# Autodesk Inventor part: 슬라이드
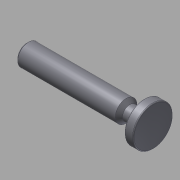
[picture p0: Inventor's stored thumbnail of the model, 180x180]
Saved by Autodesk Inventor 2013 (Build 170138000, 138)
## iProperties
Company: 한국ATC센터
Created: 2015-12
Part Number: 슬라이드
Document SubType Name: Modeling
Designer: mdu
Density: 7.86 g/cm^3
Mass: 68.0563 g
Surface Area: 34.7349 cm^2
Volume: 8.65856 cm^3
Material: 강철, 연강
Author: mdu
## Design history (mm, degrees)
sketch "스케치1"
  geometry: L1 (-35, 0)-(35, 0); L2 (35, 0)-(35, 11); L3 (35, 11)-(30, 11); L4 (30, 11)-(30, 4); L5 (30, 4)-(22, 4); L6 (22, 4)-(20, 6); L7 (20, 6)-(-35, 6); L8 (-35, 6)-(-35, 0); 1 further point
  constraints: 16 end point, 4 parallel, 2 midpoint, 2 perpendicular, 1 horizontal
  dimensions: "d0" = 70 distance of L1.start L1.end; "d1" = 12 diameter of L7 L1; "d2" = 22 diameter of L3 L1; "d3" = 5 distance of L2.end L3.end; "d4" = 8 diameter of L5 L1; "d5" = 135 deg angle of L6 L5; "d6" = 15 distance from line of L2 L6.end
revolve "회전1" sketch "스케치1" stored, may be unused: angle "d7" = 90 deg
chamfer "모따기1" distance "d8" = 1; stored, may be unused: second distance "d9" = 2, angle "d10" = 45 deg
fillet "모깎기1" dims "d11" = 0.5
node "솔리드1"
